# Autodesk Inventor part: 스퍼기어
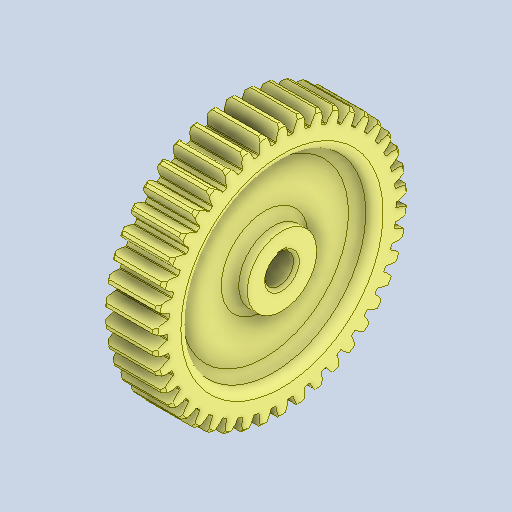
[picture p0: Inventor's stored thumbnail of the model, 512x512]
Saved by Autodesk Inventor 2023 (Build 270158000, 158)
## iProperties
Created: 2024-09
Part Number: 스퍼기어
Material: 강철, 탄소
Document SubType Name: Modeling
Designer: home
Density: 7.85 g/cm^3
Appearance: 기본값
Author: jhkim
Sending System: Autodesk Inventor 2025
Preprocessor: ST-DEVELOPER v20
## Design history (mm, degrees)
feature "솔리드1"
node "솔리드2"
